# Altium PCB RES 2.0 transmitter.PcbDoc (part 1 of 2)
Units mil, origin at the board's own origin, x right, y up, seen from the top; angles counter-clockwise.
Board outline 3335 x 2413 mil, 2 copper layers (Top Layer, Bottom Layer); 59 components, 51 nets, 223 pads, 116 vias.
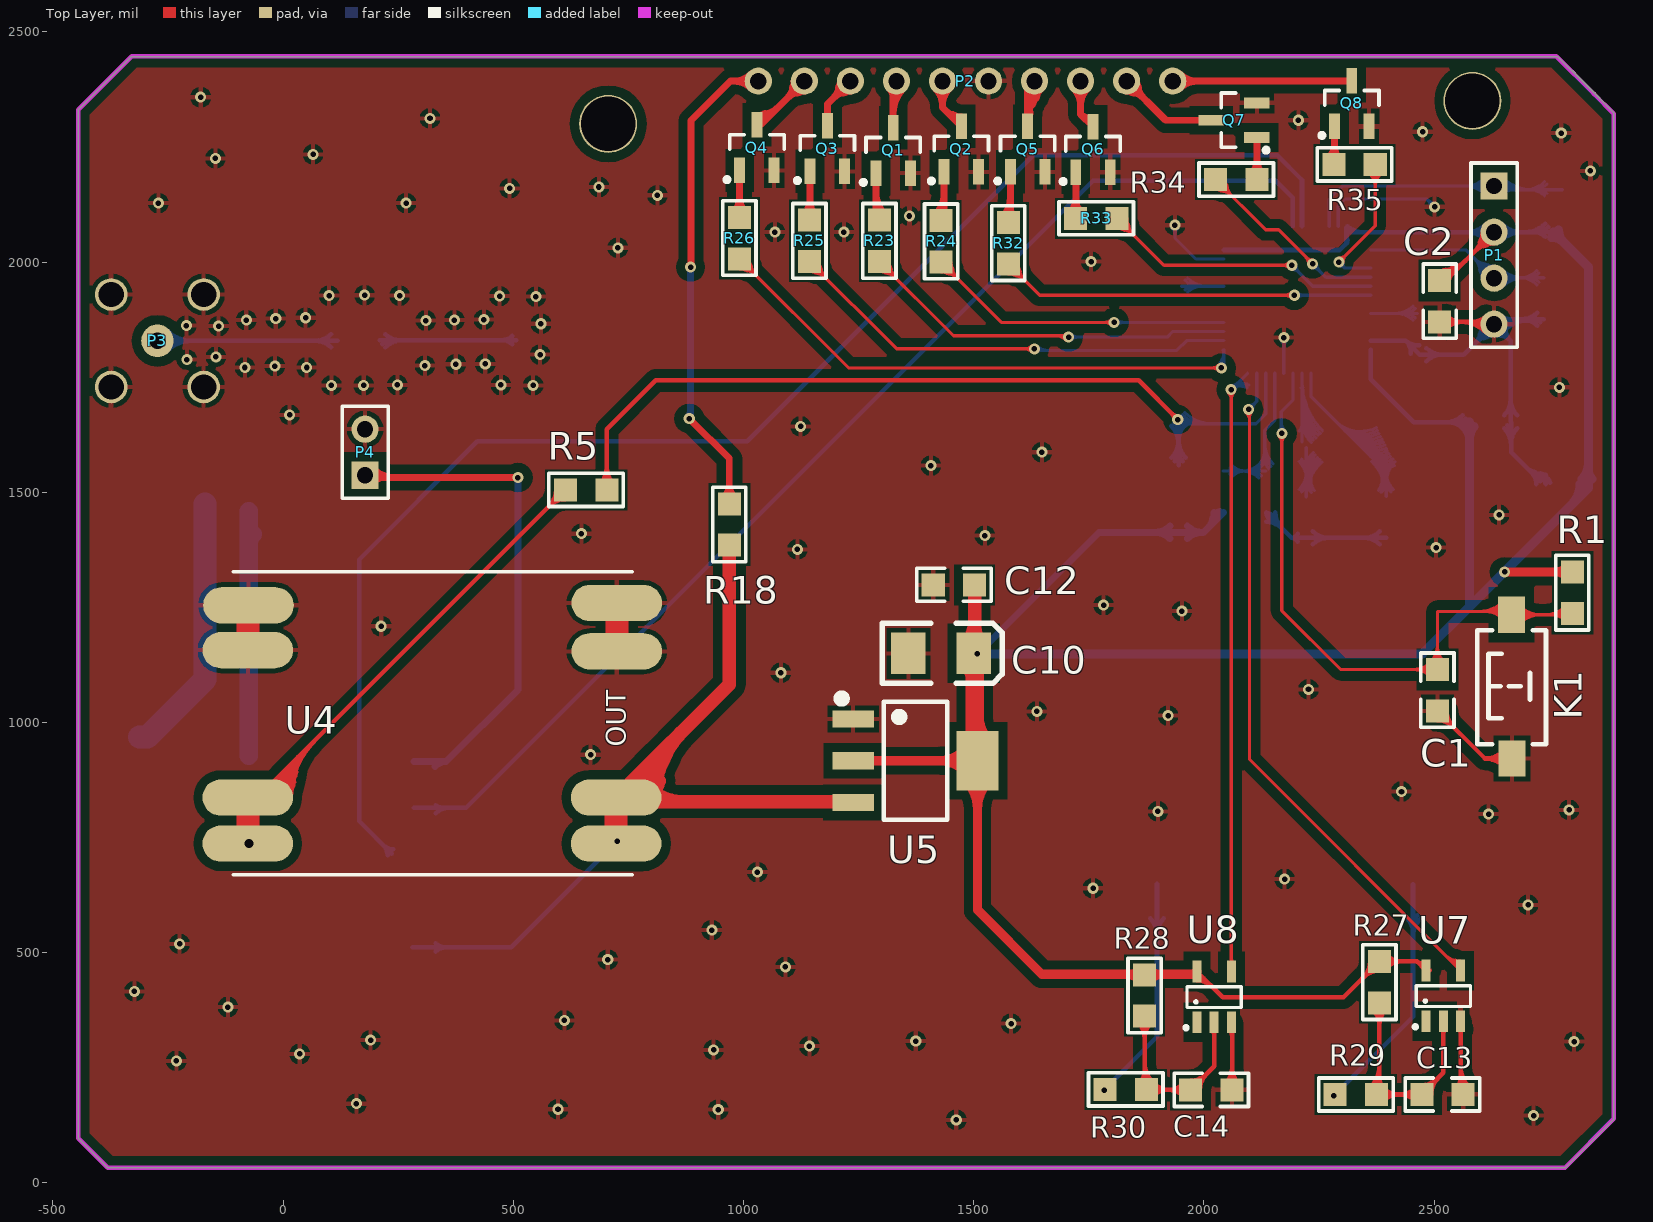
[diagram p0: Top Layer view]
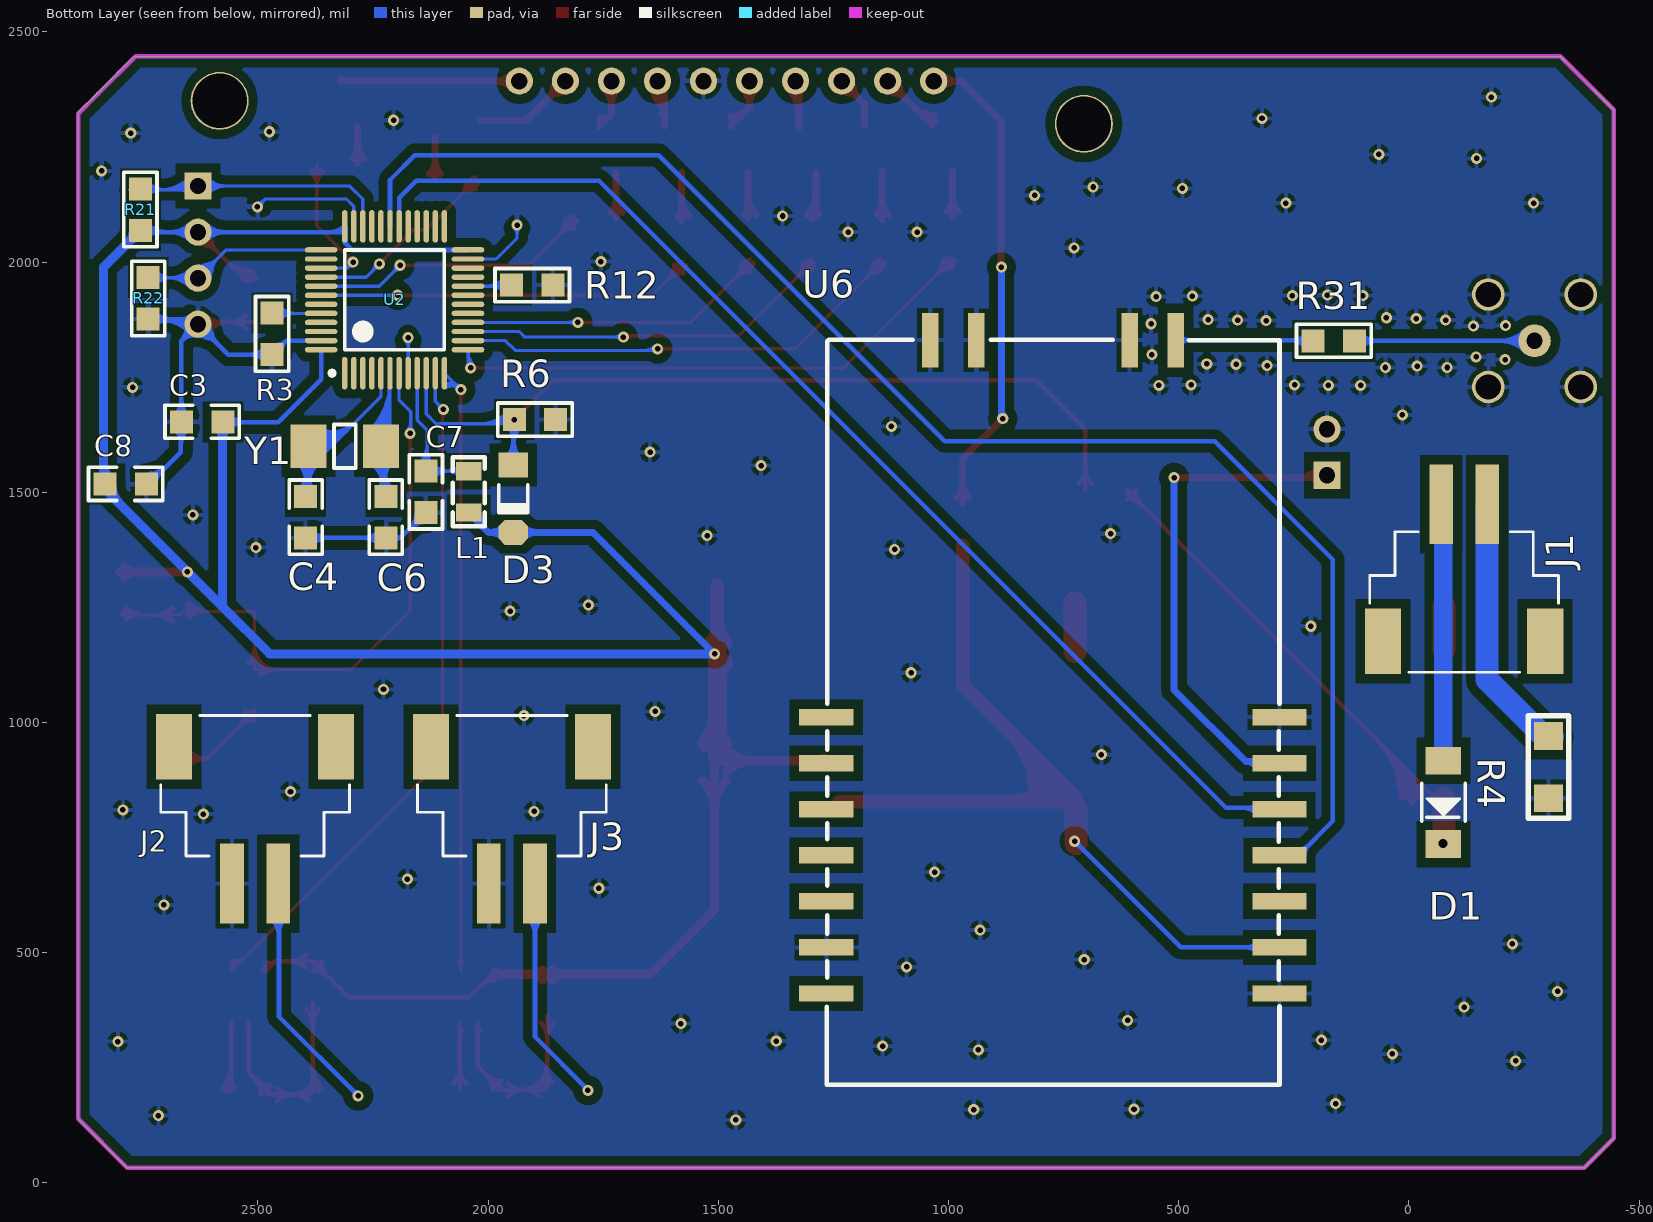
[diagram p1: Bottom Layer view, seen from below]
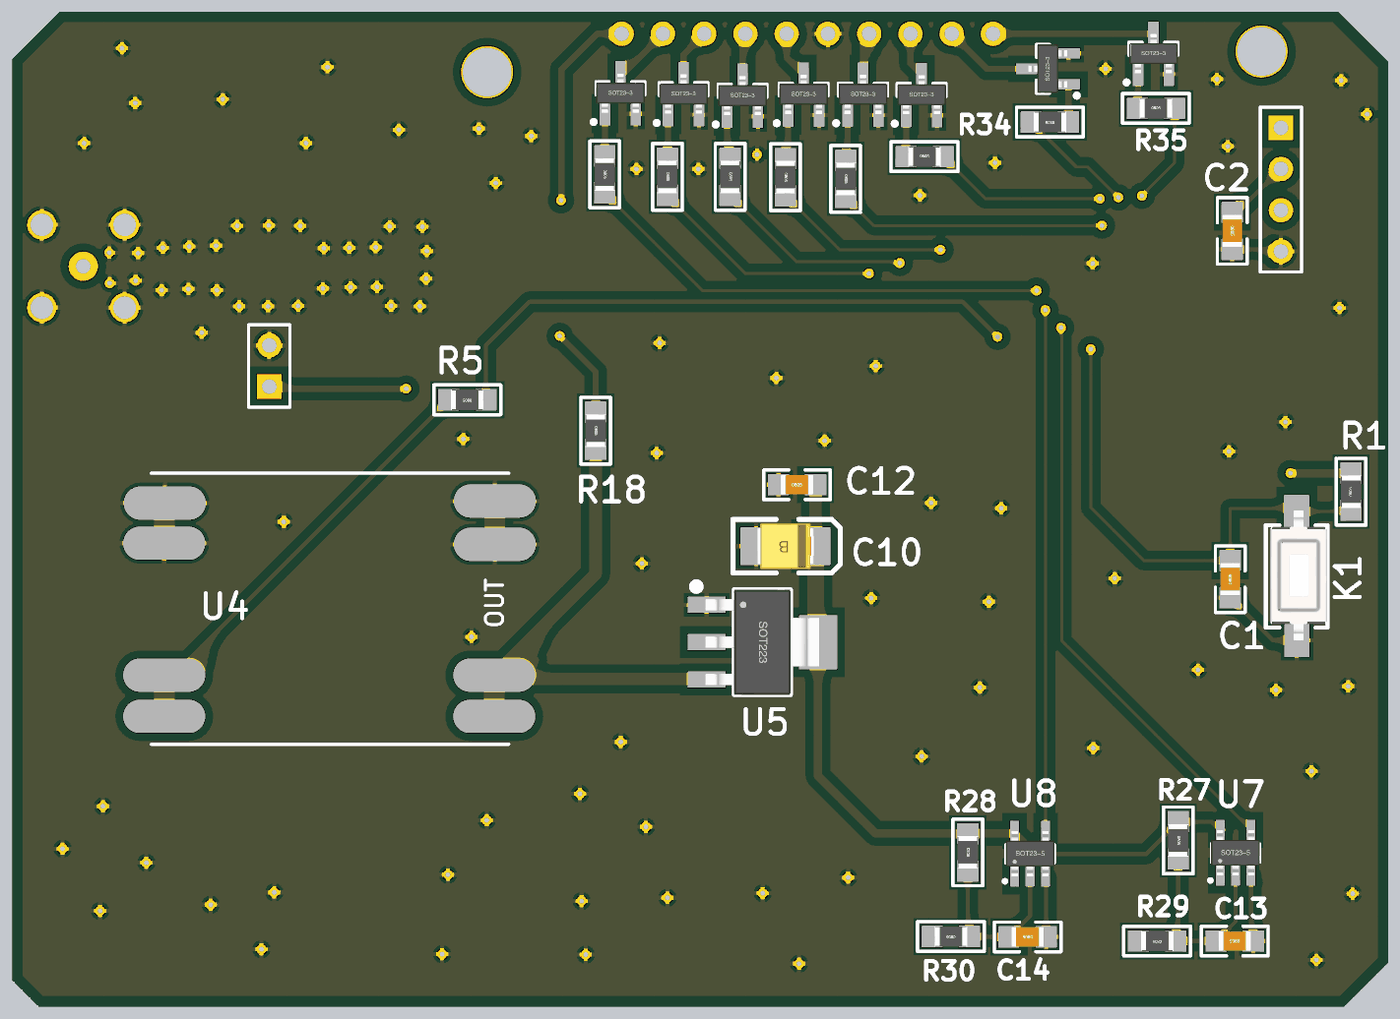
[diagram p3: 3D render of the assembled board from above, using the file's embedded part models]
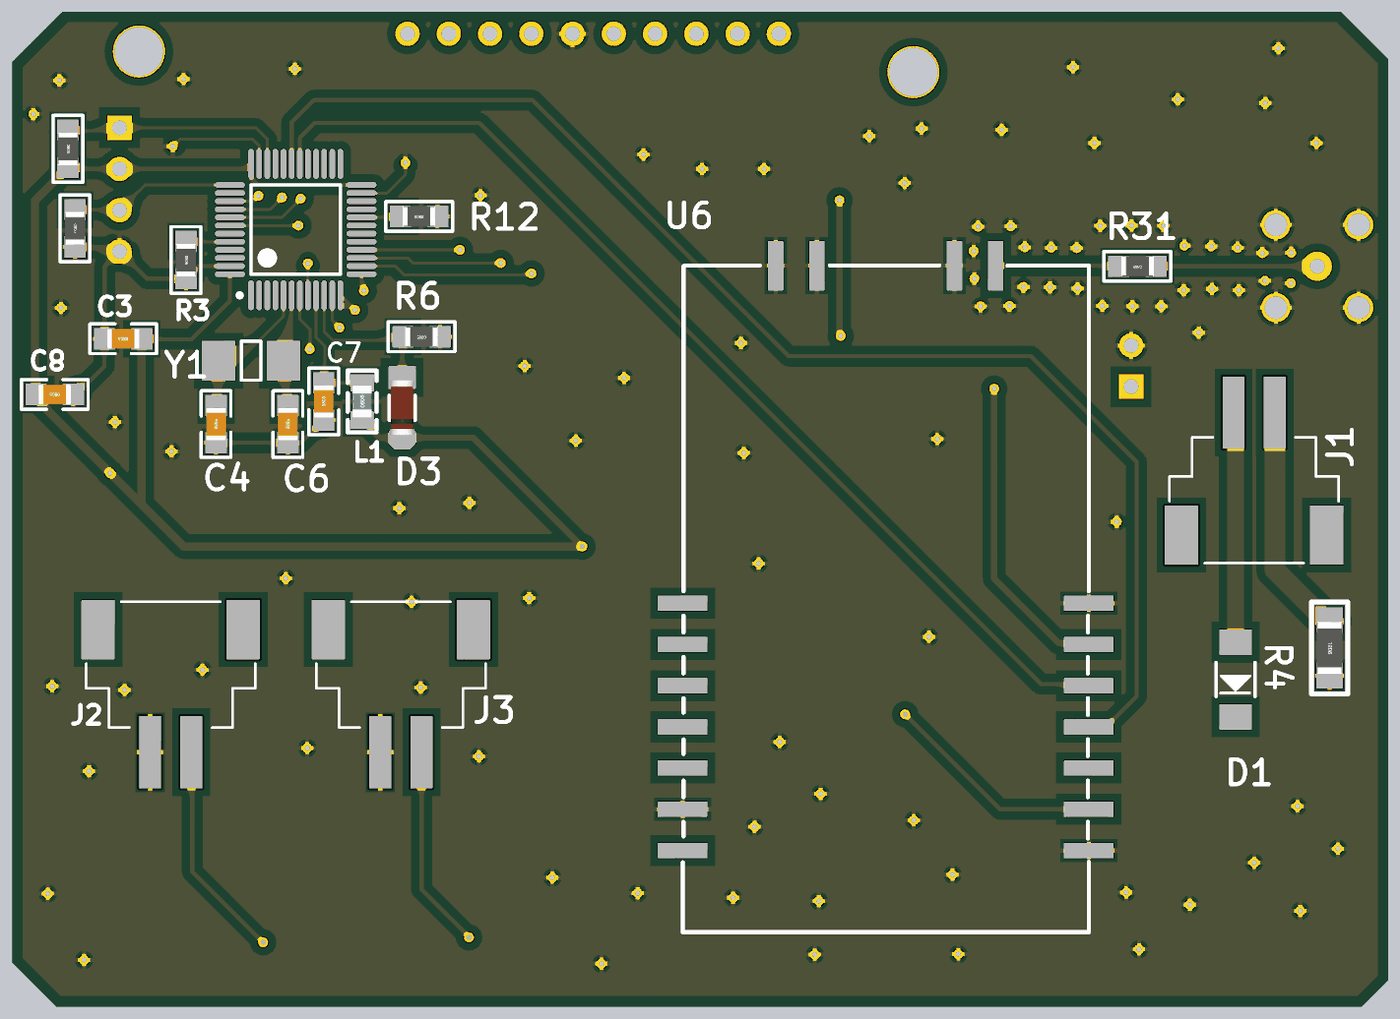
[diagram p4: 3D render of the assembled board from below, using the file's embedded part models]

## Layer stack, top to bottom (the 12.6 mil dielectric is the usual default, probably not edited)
Top Solder: solder mask 0.4, Solder Resist, Dk 3.5
Top Layer: signal copper 1.4
Dielectric1: dielectric 12.6, FR-4, Dk 4.8
Bottom Layer: signal copper 1.4
Bottom Solder: solder mask 0.4, Solder Resist, Dk 3.5

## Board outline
2890,171 2890,139 2784,33 2675,33 -381,33 -421,73 -445,97 -445,147 -445,2331 -350,2426 -330,2446 -244,2446 2769,2446 2829,2386 2890,2325 2890,2285

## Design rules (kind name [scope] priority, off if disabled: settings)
Clearance "polygon clearance" [Inpolygon] p1: gap=20 ignorepadtopadclearanceinfootprint=FALSE except(0: Arc-Hole Track-Hole SMDPad-Hole THPad-Hole Via-Hole Fill-Hole Poly-Hole Region-Hole Text-Hole)
Clearance [All] p2: gap=7 ignorepadtopadclearanceinfootprint=FALSE except(0: Arc-Hole Track-Hole SMDPad-Hole THPad-Hole Via-Hole Fill-Hole Poly-Hole Region-Hole Text-Hole)
ComponentClearance [All] p1: gap=5 collisioncheckmode=3 verticalgap=10 showdistances=FALSE
HoleSize [All] p1: absolutevalues=TRUE maxlimit=137.8 minlimit=1 maxpercent=80.000 minpercent=20.000
MinimumSolderMaskSliver [All] p1: minsoldermaskwidth=1
PasteMaskExpansion [All] p1: expansion=1
PlaneClearance [All] p1: clearance=1
PolygonConnect [All] p1: connectstyle=Relief reliefconductorwidth=10 reliefentries=4 polygonreliefangle="90 Angle" airgapwidth=10
RoutingCorners [All] p1: cornerstyle=45-Degree minsetback=1 maxsetback=10000
RoutingVias [All] p1: holewidth=15 width=15 viastyle="Through Hole" minholewidth=12 minwidth=20 maxholewidth=30 maxwidth=40
SilkToSilkClearance [All] p1: silktosilkclearance=1
SilkToSolderMaskClearance [IsPad] p1: minsilkscreentomaskgap=0.1 clearancetoexposedcopper=TRUE
SolderMaskExpansion [All] p1: expansion=3
Width [All] p1: maxlimit=50 minlimit=7 preferedwidth=10
22 further rules are at their usual default settings.

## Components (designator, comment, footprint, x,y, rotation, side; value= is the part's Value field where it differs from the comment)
C1 "Cap vol" "C 0805" 2507,1070 r90 top
C2 "Cap vol" "C 0805" 2512,1915 r270 top
C3 "Cap vol" "C 0805" 2621,1653 r0 bottom
C4 "Cap vol" "C 0805" 2396,1446 r90 bottom
C6 "Cap vol" "C 0805" 2222,1446 r90 bottom
C7 "Cap vol" "C 0805" 2135,1501 r90 bottom
C8 "Cap vol" "C 0805" 2787,1518 r0 bottom
C10 "Cap vol" "CP 3528B" 1429,1150 r180 top
C12 "Cap vol" "C 0805" 1457,1299 r0 top
C13 "Cap vol" "C 0805" 2518,192 r180 top
C14 "Cap vol" "C 0805" 2016,202 r180 top
D1 "SS14" DO-214 -75,826 r270 bottom
D3 "LL4148" LL34 1945,1486 r270 bottom
J1 "XH2.54_2P" XH2.54_2P_SMT -170,1474 r0 bottom
J2 "XH2.54_2P" XH2.54_2P_SMT 2556,650 r180 bottom
J3 "XH2.54_2P" XH2.54_2P_SMT 1998,650 r180 bottom
K1 "Key" "KEY 3.6*2.5 SMD" 2668,1079 r90 top
L1 "Inductor" "L 0805" 2042,1501 r90 bottom
P1 "Header 4" HDR1X4 2630,2165 r270 top
P2 "Header_10H" Header_10H 1032,2393 r90 top
P3 "天线插座" ANT -273,1829 r0 top
P4 "Header 2" HDR1X2 178,1537 r90 top
Q1 "Model" SOT23-3 1325,2243 r0 top
Q2 "Model" SOT23-3 1473,2246 r0 top
Q3 "Model" SOT23-3 1182,2247 r0 top
Q4 "Model" SOT23-3 1029,2249 r0 top
Q5 "Model" SOT23-3 1617,2246 r0 top
Q6 "Model" SOT23-3 1759,2245 r0 top
Q7 "Model" SOT23-3 2065,2308 r90 top
Q8 "Model" SOT23-3 2321,2345 r0 top
R1 "Res" "R 0805" 2800,1282 r90 top
R3 "Res" "R 0805" 2469,1844 r270 bottom
R4 "Res" "R 1206" -303,903 r270 bottom
R5 "Res" "R 0805" 658,1505 r180 top
R6 "Res" "R 0805" 1898,1658 r0 bottom
R12 "Res" "R 0805" 1904,1950 r0 bottom
R18 "Res" "R 0805" 969,1430 r270 top
R21 "Res" "R 0805" 2755,2114 r270 bottom
R22 "Res" "R 0805" 2738,1921 r270 bottom
R23 "Res" "R 0805" 1295,2046 r270 top
R24 "Res" "R 0805" 1429,2045 r270 top
R25 "Res" "R 0805" 1143,2046 r270 top
R26 "Res" "R 0805" 991,2052 r270 top
R27 "Res" "R 0805" 2381,436 r270 top
R28 "Res" "R 0805" 1871,407 r270 top
R29 "Res" "R 0805" 2330,192 r180 top
R30 "Res" "R 0805" 1830,203 r180 top
R31 "Res2" "R 0805" 163,1829 r0 bottom
R32 "Res" "R 0805" 1575,2041 r270 top
R33 "Res" "R 0805" 1766,2095 r0 top
R34 "Res" "R 0805" 2070,2179 r180 top
R35 "Res" "R 0805" 2327,2212 r0 top
U2 "STM32F103C8T6" LQFP48 2203,1918 r180 bottom
U4 "DM02" DM02 324,997 r180 top
U5 "AMS1117" SOT223 1373,917 r270 top
U6 "USART_Module" USART_Module 778,1121 r0 bottom
U7 "SN74LVC1G14" SOT23-5 2520,406 r0 top
U8 "SN74LVC1G14" SOT23-5 2022,404 r0 top
Y1 "Freq" XTAL-5032 2311,1600 r0 bottom

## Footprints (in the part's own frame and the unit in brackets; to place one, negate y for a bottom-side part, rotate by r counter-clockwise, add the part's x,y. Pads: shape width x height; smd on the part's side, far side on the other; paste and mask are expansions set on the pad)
ANT [mm]
  round 1.8 hole 0.9: 1(0,0)
  round 1.8 hole 1.4: 2(-2.55,2.55) 3(2.55,2.55) 4(-2.55,-2.55) 5(2.55,-2.55)
"C 0805" [mil]
  rect 50x50 smd: 1(-45,0) 2(45,0)
  silkscreen extent -81,-36 81,36, body extent -39,-24 39,24, height 20
"CP 3528B" [mil]
  rect 75x90 smd: 1(-70.86,0) 2(70.87,0)
  silkscreen extent -132,-65 128,65, body extent -69,-55 69,55, height 75
DM02 [mm]
  oval 5x2 smd: 1(-10.143,6.604) 2(-10.143,4.064) 3(-10.177,-4.001) 4(-10.177,-6.668) 5(10.143,-6.54) 6(10.177,-4.064) 7(10.177,4.064) 8(10.177,6.604)
  silkscreen extent -11.03,-8.38 10.97,8.32
DO-214 [mil]
  rect 60x76.77 smd: 1(-91.03,0) 2(90.07,0)
  silkscreen extent -42,-47 41,47, body extent -84,-47 83,47, height 118
HDR1X2 [mm] "Connector; Header; 2 Position"
  rect 1.5x1.5 hole 0.9: 1(0,0)
  round 1.5 hole 0.9: 2(2.54,0)
  silkscreen extent -1.27,-1.27 3.81,1.27
HDR1X4 [mm] "Connector; Header; 4 Position"
  rect 1.5x1.5 hole 0.9: 1(0,0)
  round 1.5 hole 0.9: 2(2.54,0) 3(5.08,0) 4(7.62,0)
  silkscreen extent -1.27,-1.27 8.89,1.27
Header_10H [mm]
  round 1.5 hole 0.9: 1(0,0) 2(0,-2.54) 3(0,-5.08) 4(0,-7.62) 5(0,-10.16) 6(0,-12.7) 7(0,-15.24) 8(0,-17.78) 9(0,-20.32) 10(0,-22.86)
"KEY 3.6*2.5 SMD" [mm]
  rect 2x1.5 smd: 1(-3.996,-0.02) 2(3.937,0)
  silkscreen extent -3.21,-1.9 3.09,1.9, body extent -4,-1.88 4,1.62, height 2.59
"L 0805" [mil]
  rect 40x55 smd: 1(-45,0) 2(45,0)
  silkscreen extent -75,-35 75,35, body extent -39,-24 39,24, height 35
LL34 [mm]
  rect 1.37x1.62 smd: 1(-1.855,0)
  oct 1.37x1.62 smd: 2(1.855,0)
  silkscreen extent -0.76,-0.8 0.78,0.8, body extent -1.7,-0.75 1.7,0.75, height 1.5
LQFP48 [mm]
  oval 0.3x1.8 smd: 1(-2.75,-4.05) 2(-2.25,-4.05) 3(-1.75,-4.05) 4(-1.25,-4.05) 5(-0.75,-4.05) 6(-0.25,-4.05) 7(0.25,-4.05) 8(0.75,-4.05) 9(1.25,-4.05) 10(1.75,-4.05) 11(2.25,-4.05) 12(2.75,-4.05) 25(2.75,4.05) 26(2.25,4.05) 27(1.75,4.05) 28(1.25,4.05) 29(0.75,4.05) 30(0.25,4.05) 31(-0.25,4.05) 32(-0.75,4.05) 33(-1.25,4.05) 34(-1.75,4.05) 35(-2.25,4.05) 36(-2.75,4.05)
  oval 1.8x0.3 smd: 13(4.05,-2.75) 14(4.05,-2.25) 15(4.05,-1.75) 16(4.05,-1.25) 17(4.05,-0.75) 18(4.05,-0.25) 19(4.05,0.25) 20(4.05,0.75) 21(4.05,1.25) 22(4.05,1.75) 23(4.05,2.25) 24(4.05,2.75) 37(-4.05,2.75) 38(-4.05,2.25) 39(-4.05,1.75) 40(-4.05,1.25) 41(-4.05,0.75) 42(-4.05,0.25) 43(-4.05,-0.25) 44(-4.05,-0.75) 45(-4.05,-1.25) 46(-4.05,-1.75) 47(-4.05,-2.25) 48(-4.05,-2.75)
  silkscreen extent -3.58,-4.17 2.75,2.75, body extent -3.5,-3.5 3.5,3.5, height 1.6
"R 0805" [mil]
  rect 50x50 smd: 1(-45,0) 2(45,0)
  silkscreen extent -81,-36 81,36, body extent -39,-25 39,25, height 20
"R 1206" [mil]
  rect 60x62.99 smd: 1(-67.5,0) 2(67.5,0)
  silkscreen extent -111,-44 112,44, body extent -63,-31 63,31, height 22
SOT23-3 [mm]
  rect 0.6x1.4 smd: 1(-0.95,-1.27) 2(0.95,-1.27) 3(0,1.244)
  silkscreen extent -1.78,-1.9 1.5,0.7, body extent -1.5,-1.2 1.5,1.2, height 1.05
SOT23-5 [mm]
  rect 0.5x1.2 smd: 1(-0.95,-1.4) 2(0,-1.4) 3(0.95,-1.4) 4(0.95,1.4) 5(-0.95,1.4)
  silkscreen extent -1.63,-1.78 1.5,0.56, body extent -1.5,-1.4 1.5,1.4, height 1.15
SOT223 [mm]
  rect 0.95x2.3 smd: 1(-2.3,-3.429) 2(0,-3.429) 3(2.3,-3.429)
  rect 3.3x2.3 smd: 2(0,3.429)
  silkscreen extent -3.63,-4.26 3.25,1.75, body extent -3.25,-3.51 3.25,3.51, height 1.65
USART_Module [mm]
  rect 3x0.9 smd: 1(-12.627,2.78) 2(-12.627,5.32) 3(-12.627,7.86) 4(-12.627,10.4) 5(-12.627,12.94) 6(-12.627,15.48) 7(-12.627,18.02) 8(12.373,18.02) 9(12.373,15.48) 10(12.373,12.94) 11(12.373,10.4) 12(12.373,7.86) 13(12.373,2.78) 14(12.373,5.32)
  rect 0.9x3 smd: 15(6.643,-18.02) 16(4.103,-18.02) 17(-4.357,-18.02) 18(-6.897,-18.02)
  silkscreen extent -12.63,-18.03 12.36,23.05
XH2.54_2P_SMT [mm]
  rect 1.3x4.4 smd mask+0.152: 1(0,0) 2(2.54,0)
  rect 2x3.6 smd mask+0.152: 3(5.74,7.554)
  rect 2x3.6 smd: 4(-3.2,7.554)
  silkscreen extent -3.94,1.52 6.48,9.27
XTAL-5032 [mm]
  rect 2x2.4 smd: 1(-2,0) 2(2,0)
  silkscreen extent -0.6,-1.2 0.6,1.2, body extent -2.6,-1.7 2.6,1.7, height 3.4

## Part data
C1 C2 C3 C4 C6 C7 C8 C12 C13 C14: library part Cap, "无极性电容"
C10: library part Cap_Pol, "极性电容"
D1: library part Diode, "肖特基（快恢复）二极管"
D3: library part Diode, "开关二极管"
J1: "XH2.54Header,2-pin"
K1: "按键"
L1: "电感"
P1: "Header, 4-Pin"
P4: "Header, 2-Pin"
Q1 Q2 Q3 Q4 Q5 Q6 Q7 Q8: library part Transistor_NPN, "NPN三极管"
R1 R3 R4 R5 R6 R12 R18 R21 R22 R23 R24 R25 R26 R27 R28 R29 R30 R32 R33 R34 R35: library part Resistor, "电阻"
R31: "Resistor"
U2: "Micro controller"
U4: "开关型DC-DC变换器"
U5: "线性稳压器"
U6: library part RES
U7 U8: "单路施密特反相器"
Y1: library part XTAL, "晶振"

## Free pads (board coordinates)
  round 125.98 hole 118.11: 1(706,2300) 2(2583,2350)

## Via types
v1: diameter 24, hole 12, Top Layer to Bottom Layer, 115 vias
v2: diameter 40, hole 20, Top Layer to Bottom Layer, 1 vias

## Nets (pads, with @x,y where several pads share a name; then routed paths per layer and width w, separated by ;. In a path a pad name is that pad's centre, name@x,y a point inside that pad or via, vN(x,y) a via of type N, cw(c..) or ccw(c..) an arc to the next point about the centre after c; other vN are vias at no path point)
ADC: D3.1 R5.1 R6.2 U2.10 | length 3224.3
  Top Layer w10: R5.1@703,1505 703,1637 809,1743 1858,1743 v1(1943,1658) ; 703,1553.28 cw(c654.72,1553.28) 688.86,1519.14 ccw(c654.72,1553.28) 703,1553.28 ; 703,1553.28 ccw(c751.28,1553.28) 717.14,1519.14 cw(c751.28,1553.28) 703,1553.28 ; 1931.05,1669.95 cw(c1919.1,1658) 1936,1658 ccw(c1919.1,1658) 1931.05,1669.95 ; 1931.05,1669.95 ccw(c1943,1681.9) 1943,1665 cw(c1943,1681.9) 1931.05,1669.95
  Bottom Layer w7: v1(1943,1658) 1952,1649 2113,1649 2134.1,1670.1 U2.10@2134.1,1758.55 ; R6.2@1947.21,1650.62 cw(c1952.95,1640.57) R6.2@1958.73,1650.59 ; R6.2@1948.43,1651.46 cw(c1959.34,1638.33) R6.2@1967.88,1653.12 ; R6.2@1951.21,1660.2 ccw(c1966.25,1664.23) R6.2@1958.47,1650.74 ; R6.2@1959.18,1658.14 ccw(c1952.5,1646.57) R6.2@1943.96,1656.85 ; R6.2@1943.94,1656.83 cw(c1951.59,1647.28) R6.2@1957.7,1657.88 ; R6.2@1943.94,1656.83 cw(c1951.59,1647.28) R6.2@1957.7,1657.88 ; R6.2@1943.94,1656.83 cw(c1951.59,1647.28) R6.2@1957.7,1657.88 ; R6.2@1948.31,1651.37 cw(c1958.46,1638.7) R6.2@1966.57,1652.76 ; R6.2@1948.31,1651.37 cw(c1958.46,1638.7) R6.2@1966.57,1652.76 ; R6.2@1948.31,1651.37 cw(c1958.46,1638.7) R6.2@1966.57,1652.76 ; R6.2@1939.11,1654.11 ccw(c1951.45,1666.45) 1951.45,1649 cw(c1951.45,1666.45) R6.2@1939.11,1654.11 ; R6.2@1944.06,1659.06 ccw(c1968.35,1683.35) 1968.35,1649 cw(c1968.35,1683.35) R6.2@1944.06,1659.06 ; R6.2@1948.3,1663.3 ccw(c1982.83,1697.83) 1982.83,1649 cw(c1982.83,1697.83) R6.2@1948.3,1663.3 ; R6.2@1949.01,1664.01 ccw(c1985.25,1700.25) 1985.25,1649 cw(c1985.25,1700.25) R6.2@1949.01,1664.01 ; R6.2@1953.25,1668.25 ccw(c1999.73,1714.73) 1999.73,1649 cw(c1999.73,1714.73) R6.2@1953.25,1668.25 ; R6.2@1958.2,1642.8 cw(c1973.18,1627.82) 1973.18,1649 ccw(c1973.18,1627.82) R6.2@1958.2,1642.8 ; R6.2@1958.2,1673.2 ccw(c2016.63,1731.63) 2016.63,1649 cw(c2016.63,1731.63) R6.2@1958.2,1673.2
  Bottom Layer w10: D3.1@1945,1559.03 R6.2@1945,1656 ; 1945,1587.93 cw(c1916.11,1587.93) 1936.54,1567.49 ccw(c1916.11,1587.93) 1945,1587.93 ; 1945,1587.93 ccw(c1973.89,1587.93) 1953.46,1567.49 cw(c1973.89,1587.93) 1945,1587.93 ; 1945,1612.07 cw(c1891.96,1612.07) 1929.47,1574.57 ccw(c1891.96,1612.07) 1945,1612.07 ; 1945,1612.07 ccw(c1998.04,1612.07) 1960.53,1574.57 cw(c1998.04,1612.07) 1945,1612.07 ; R6.2@1928.86,1643.86 cw(c1889.89,1604.89) 1945,1604.89 ccw(c1889.89,1604.89) R6.2@1928.86,1643.86 ; R6.2@1935.93,1650.93 cw(c1914.03,1629.03) 1945,1629.03 ccw(c1914.03,1629.03) R6.2@1935.93,1650.93 ; R6.2@1938.05,1653.05 cw(c1921.27,1636.27) 1945,1636.27 ccw(c1921.27,1636.27) R6.2@1938.05,1653.05 ; 1945,1614.54 cw(c1986.46,1614.54) 1957.14,1643.86 ccw(c1986.46,1614.54) 1945,1614.54 ; R6.2@1945,1645.93 cw(c1955.07,1645.93) 1947.95,1653.05 ccw(c1955.07,1645.93) R6.2@1945,1645.93
ANT: P3.1 R31.1 | length 928.5
  Bottom Layer w10: P3.1@-273,1829 R31.1@118,1829 ; -223.67,1829 cw(c-223.67,1878.33) -258.55,1843.45 ccw(c-223.67,1878.33) -223.67,1829 ; -223.67,1829 ccw(c-223.67,1779.67) -258.55,1814.55 cw(c-223.67,1779.67) -223.67,1829 ; -199.53,1829 cw(c-199.53,1902.47) -251.48,1850.52 ccw(c-199.53,1902.47) -199.53,1829 ; -199.53,1829 ccw(c-199.53,1755.53) -251.48,1807.48 cw(c-199.53,1755.53) -199.53,1829 ; 69.72,1829 cw(c69.72,1780.72) 103.86,1814.86 ccw(c69.72,1780.72) 69.72,1829 ; 69.72,1829 ccw(c69.72,1877.28) 103.86,1843.14 cw(c69.72,1877.28) 69.72,1829
BLUE: P2.3 Q3.3 | length 355.8
  Top Layer w15: Q3.3@1182,2295.97 1182,2343 P2.3@1232,2393 ; 1205.88,2377.71 cw(c1236.83,2369.42) P2.3@1230.4,2400.81 ; 1216.71,2366.88 ccw(c1208.42,2397.83) P2.3@1239.81,2391.4 ; 1194.4,2355.4 cw(c1232,2317.79) 1232,2370.97 ccw(c1232,2317.79) 1194.4,2355.4 ; 1194.4,2355.4 ccw(c1156.79,2393) 1209.97,2393 cw(c1156.79,2393) 1194.4,2355.4
GND_D: C1.1 C2.2 C3.2 C4.1 C6.1 C7.1 C8.1 C10.2 C12.1 C13.1 C14.1 J2.1 J3.1 K1.1 P1.4 P2.6 P3.2 P3.3 P3.4 P3.5 P4.2 Q1.2 Q2.2 Q3.2 Q4.2 Q5.2 Q6.2 Q7.2 Q8.2 R3.2 R4.2 R6.1 R12.1 R22.2 U2.8 U2.23 U2.35 U2.47 U4.3 U4.4 U4.5 U4.6 U5.1 U6.1 U6.7 U6.9 U6.15 U6.16 U6.17 U7.3 U8.3 | length 6865.7
  Top Layer w10: C14.1@2061,202 U8.3@2061,347.29 ; C2.2@2512,1870 P1.4@2625,1870 ; 2532.2,998.25 cw(c2541.24,1032.01) C1.1@2507,1025 ; 2533.75,999.8 ccw(c2499.99,990.76) C1.1@2507,1025 ; C13.1@2557.4,197.6 U7.3@2557.4,350.89 ; K1.1@2668.79,921.69 2610.31,921.69 ; 2061,250.28 cw(c2012.72,250.28) 2046.86,216.14 ccw(c2012.72,250.28) 2061,250.28 ; 2061,250.28 ccw(c2109.28,250.28) 2075.14,216.14 cw(c2109.28,250.28) 2061,250.28 ; C1.1@2507,1025 2610.31,921.69 ; 2541.14,990.86 cw(c2575.28,1025) 2527,1025 ccw(c2575.28,1025) 2541.14,990.86 ; 2541.14,990.86 ccw(c2507,956.72) 2507,1005 cw(c2507,956.72) 2541.14,990.86 ; 2557.4,325.41 cw(c2569.1,325.41) 2560.83,333.68 ccw(c2569.1,325.41) 2557.4,325.41 ; 2557.4,325.41 ccw(c2545.71,325.41) 2553.98,333.68 cw(c2545.71,325.41) 2557.4,325.41 ; 2560.28,1870 cw(c2560.28,1918.28) 2526.14,1884.14 ccw(c2560.28,1918.28) 2560.28,1870 ; 2560.28,1870 ccw(c2560.28,1821.72) 2526.14,1855.86 cw(c2560.28,1821.72) 2560.28,1870 ; 2582.86,1870 cw(c2582.86,1817.86) 2619.73,1854.73 ccw(c2582.86,1817.86) 2582.86,1870 ; 2582.86,1870 ccw(c2582.86,1912.14) 2612.66,1882.34 cw(c2582.86,1912.14) 2582.86,1870 ; 2610.32,921.69 cw(c2610.32,864.26) 2651.29,904.5 ccw(c2610.32,864.26) 2610.32,921.69 ; 2610.32,921.69 ccw(c2610.32,979.11) 2651.29,938.87 cw(c2610.32,979.11) 2610.32,921.69 ; 2634.16,921.69 cw(c2634.16,887.67) 2658.42,911.51 ccw(c2634.16,887.67) 2634.16,921.69 ; 2634.16,921.69 ccw(c2634.16,955.7) 2658.42,931.87 cw(c2634.16,955.7) 2634.16,921.69 ; U8.3@2055.98,331.68 cw(c2043.86,319.56) 2061,319.56 ccw(c2043.86,319.56) U8.3@2055.98,331.68 ; C13.1@2548.86,206.14 ccw(c2528.22,226.78) 2557.4,226.78 cw(c2528.22,226.78) C13.1@2548.86,206.14 ; 2557.4,229.65 ccw(c2600.65,229.65) 2570.07,199.07 cw(c2600.65,229.65) 2557.4,229.65 ; 2557.4,253.79 ccw(c2624.79,253.79) 2577.14,206.14 cw(c2624.79,253.79) 2557.4,253.79 ; 2558.71,1870 cw(c2558.71,1793.71) 2612.66,1847.66 ccw(c2558.71,1793.71) 2558.71,1870
  Top Layer w50: U4.6@-76.69,1157 U4.5@-76.69,1253.13 ; U4.3@724.69,1154.5 U4.4@724.69,1259.5
  Bottom Layer w7: v1(1937,2080) 1937,2052 1982.42,2006.58 U2.23@2043.55,2006.58 ; U2.8@2173.47,1758.55 v1@2173.47,1840.53 ; U2.35@2291.58,2077.45 2291.58,2121.29 2307.29,2137 2484,2137 v1(2501,2120) ; 1937,2059.48 cw(c1957.52,2059.48) 1943.01,2073.99 ccw(c1957.52,2059.48) 1937,2059.48 ; 1937,2059.48 ccw(c1916.48,2059.48) 1930.99,2073.99 cw(c1916.48,2059.48) 1937,2059.48 ; 2173.47,1815.48 cw(c2193.99,1815.48) 2179.48,1829.99 ccw(c2193.99,1815.48) 2173.47,1815.48 ; 2173.47,1815.48 ccw(c2152.95,1815.48) 2167.46,1829.99 cw(c2152.95,1815.48) 2173.47,1815.48 ; 2486.49,2134.51 cw(c2471.98,2120) 2492.5,2120 ccw(c2471.98,2120) 2486.49,2134.51 ; 2486.49,2134.51 ccw(c2501,2149.02) 2501,2128.5 cw(c2501,2149.02) 2486.49,2134.51
  Bottom Layer w10: 2160.2,1429.25 cw(c2169.24,1463.01) C7.1@2135,1456 ; 2161.75,1430.8 ccw(c2127.99,1421.76) C7.1@2135,1456 ; U2.47@2362.45,1829.42 2438.58,1829.42 ; C4.1@2396,1401 C6.1@2222,1401 2190,1401 ; 2599.48,1842.65 cw(c2636.61,1832.7) P1.4@2628.9,1870.36 ; 2607.65,1834.48 ccw(c2597.7,1871.61) P1.4@2635.36,1863.9 ; C3.2@2666,1653 2666,1829 ; C3.2@2667,1652 2667,1587 C8.1@2730,1524 ; 2713.24,1545.71 cw(c2702.56,1505.84) C8.1@2742,1518 ; C8.1@2730.72,1541.02 cw(c2722.98,1512.14) C8.1@2751.56,1520.95 ; R22.2@2738,1876 2641,1876 P1.4@2630,1865 ; C7.1@2135,1456 2190,1401 ; 2169.14,1421.86 cw(c2203.28,1456) 2155,1456 ccw(c2203.28,1456) 2169.14,1421.86 ; 2169.14,1421.86 ccw(c2135,1387.72) 2135,1436 cw(c2135,1387.72) 2169.14,1421.86 ; 2190,1401 cw(c2190,1385.4) 2204.02,1392.24 ccw(c2190,1385.4) 2190,1401 ; 2190,1401 ccw(c2190,1416.6) 2204.02,1409.76 cw(c2190,1416.6) 2190,1401 ; 2270.28,1401 cw(c2270.28,1449.28) 2236.14,1415.14 ccw(c2270.28,1449.28) 2270.28,1401 ; 2270.28,1401 ccw(c2270.28,1352.72) 2236.14,1386.86 cw(c2270.28,1352.72) 2270.28,1401 ; 2347.72,1401 cw(c2347.72,1352.72) 2381.86,1386.86 ccw(c2347.72,1352.72) 2347.72,1401 ; 2347.72,1401 ccw(c2347.72,1449.28) 2381.86,1415.14 cw(c2347.72,1449.28) 2347.72,1401 ; 2438.58,1829.42 cw(c2412.95,1803.78) 2449.07,1800.7 ccw(c2412.95,1803.78) 2438.58,1829.42 ; 2438.58,1829.42 ccw(c2464.22,1855.05) 2467.3,1818.93 cw(c2464.22,1855.05) 2438.58,1829.42 ; 2438.58,1829.42 R3.2@2469,1799 2564,1799 P1.4@2630,1865 ; 2517.28,1799 cw(c2517.28,1847.28) 2483.14,1813.14 ccw(c2517.28,1847.28) 2517.28,1799 ; 2517.28,1799 ccw(c2517.28,1750.72) 2483.14,1784.86 cw(c2517.28,1750.72) 2517.28,1799 ; 2588.13,1823.13 cw(c2630,1781.26) 2630,1840.47 ccw(c2630,1781.26) 2588.13,1823.13 ; 2588.13,1823.13 ccw(c2546.26,1865) 2605.47,1865 cw(c2546.26,1865) 2588.13,1823.13 ; 2605.2,1840.2 cw(c2630,1815.4) 2630,1850.47 ccw(c2630,1815.4) 2605.2,1840.2 ; 2605.2,1840.2 ccw(c2580.4,1865) 2615.47,1865 cw(c2580.4,1865) 2605.2,1840.2 ; P1.4@2630,1865 2666,1829 ; 2651.32,1843.68 cw(c2668.31,1860.67) 2644.44,1863.37 ccw(c2668.31,1860.67) 2651.32,1843.68 ; 2651.32,1843.68 ccw(c2634.33,1826.69) 2631.63,1850.56 cw(c2634.33,1826.69) 2651.32,1843.68 ; 2666,1701.28 cw(c2617.72,1701.28) 2651.86,1667.14 ccw(c2617.72,1701.28) 2666,1701.28 ; 2666,1701.28 ccw(c2714.28,1701.28) 2680.14,1667.14 cw(c2714.28,1701.28) 2666,1701.28 ; 2666,1829 cw(c2694.69,1857.69) 2654.37,1862.25 ccw(c2694.69,1857.69) 2666,1829 ; 2666,1829 ccw(c2637.31,1800.31) 2632.75,1840.63 cw(c2637.31,1800.31) 2666,1829 ; 2689.72,1876 cw(c2689.72,1827.72) 2723.86,1861.86 ccw(c2689.72,1827.72) 2689.72,1876 ; 2689.72,1876 ccw(c2689.72,1924.28) 2723.86,1890.14 cw(c2689.72,1924.28) 2689.72,1876 ; 2693.95,1872.25 cw(c2699.49,1840.02) R22.2@2723.39,1862.35 ; 2693.95,1872.25 cw(c2699.49,1840.02) R22.2@2723.39,1862.35 ; 2693.95,1872.25 cw(c2699.49,1840.02) R22.2@2723.39,1862.35 ; 2698.73,1873.07 ccw(c2692.73,1907.99) R22.2@2721.67,1887.54 ; 2698.73,1873.07 ccw(c2692.73,1907.99) R22.2@2721.67,1887.54 ; 2698.73,1873.07 ccw(c2692.73,1907.99) R22.2@2721.67,1887.54 ; 2712.22,1875.39 cw(c2715.69,1855.16) R22.2@2730.69,1869.17 ; 2712.22,1875.39 cw(c2715.69,1855.16) R22.2@2730.69,1869.17 ; 2712.22,1875.39 cw(c2715.69,1855.16) R22.2@2730.69,1869.17 ; P1.4@2633.2,1861.8 cw(c2667.49,1827.51) 2667.49,1876 ccw(c2667.49,1827.51) P1.4@2633.2,1861.8 ; P1.4@2640.27,1854.73 cw(c2691.63,1803.37) 2691.63,1876 ccw(c2691.63,1803.37) P1.4@2640.27,1854.73 ; P1.4@2647.34,1847.66 cw(c2715.77,1779.23) 2715.77,1876 ccw(c2715.77,1779.23) P1.4@2647.34,1847.66 ; P1.4@2647.34,1882.34 ccw(c2662.66,1897.66) 2662.66,1876 cw(c2662.66,1897.66) P1.4@2647.34,1882.34 ; C3.2@2651.86,1638.86 cw(c2615.3,1602.3) 2667,1602.3 ccw(c2615.3,1602.3) C3.2@2651.86,1638.86 ; C3.2@2658.93,1645.93 cw(c2639.44,1626.44) 2667,1626.44 ccw(c2639.44,1626.44) C3.2@2658.93,1645.93 ; 2667,1607.13 cw(c2711.87,1607.13) 2680.14,1638.86 ccw(c2711.87,1607.13) 2667,1607.13 ; 2697.62,1556.38 ccw(c2742,1600.77) 2742,1538 cw(c2742,1600.77) 2697.62,1556.38 ; 2712.1,1541.9 cw(c2688.2,1518) 2722,1518 ccw(c2688.2,1518) 2712.1,1541.9 ; 2714.69,1539.31 ccw(c2742,1566.63) 2742,1528 cw(c2742,1566.63) 2714.69,1539.31
  other v1: 1462,137 2716,146 945,159 597,160 159,172 -232,265 36,280 935,289 1143,297 2804,307 1374,308 190,310 1581,346 611,353 -120,382 -323,416 1091,469 705,485 -225,519 931,549 2704,604 1759,640 2175,660 1030,675 2618,801 1900,807 2793,810 2429,850 668,930 1922,1015 1637,1024 2227,1072 1081,1108 213,1209 1952,1242 1782,1255 1117,1376 2504,1380 1524,1406 648,1410 2641,1451 1407,1558 1648,1587 1124,1643 14,1668 2772,1728 105,1732 175,1732 543,1732 248,1733 473,1733 -83,1771 51,1771 -18,1774 308,1775 375,1778 439,1779 -209,1788 -146,1794 558,1799 2173.47,1836 -140,1861 -210,1862 560,1866 310,1873 -80,1874 372,1874 436,1875 -16,1877 49,1879 549,1925 470,1926 100,1927 253,1927 177,1928 1755,2001 727,2031 1068,2065 1218,2065 1360,2100 -271,2128 267,2128 813,2145 492,2160 686,2163 2839,2198 -147,2225 65,2234 2776,2280 2475,2283 2205,2308 319,2312 -179,2358
GREEN: P2.4 Q1.3 | length 335.2
  Top Layer w15: Q1.3@1325,2291.97 1325,2386 P2.4@1332,2393 ; P2.4@1316.42,2377.42 cw(c1295.71,2356.71) 1325,2356.71 ccw(c1295.71,2356.71) P2.4@1316.42,2377.42 ; 1325,2322.93 cw(c1402.07,2322.93) 1347.58,2377.42 ccw(c1402.07,2322.93) 1325,2322.93 ; 1325,2359.15 cw(c1365.85,2359.15) 1336.97,2388.03 ccw(c1365.85,2359.15) 1325,2359.15
KEY1: U2.11 U7.4 | length 1838.4
  Top Layer w7: v1@2099,1680 2099,919.53 U7.4@2557.4,461.12 ; 2529.91,488.61 cw(c2520.54,453.62) 2551.91,471.73 ccw(c2540.53,465.16) 2543.93,477.85 ; 2542.63,478.2 ccw(c2546.13,491.29) U7.4@2553.81,480.13 ; 2546.24,484.24 cw(c2541.23,465.56) U7.4@2557.97,475.23 ; v1@2090.99,1673.99 cw(c2071.65,1654.65) 2099,1654.65 ccw(c2071.65,1654.65) v1@2090.99,1673.99 ; 2099,1664.31 cw(c2112.69,1664.31) 2103.01,1673.99 ccw(c2112.69,1664.31) 2099,1664.31 ; 2523.05,495.47 ccw(c2557.4,529.82) 2557.4,481.24 cw(c2557.4,529.82) 2523.05,495.47 ; 2535,483.52 ccw(c2557.4,505.92) 2557.4,474.24 cw(c2557.4,505.92) 2535,483.52 ; 2546.95,471.57 ccw(c2557.4,482.02) 2557.4,467.24 cw(c2557.4,482.02) 2546.95,471.57
  Bottom Layer w7: v1(2097,1680) 2114.42,1697.42 U2.11@2114.42,1758.55 ; 2111.51,1694.51 cw(c2097,1709.02) 2097,1688.5 ccw(c2097,1709.02) 2111.51,1694.51 ; 2111.51,1694.51 ccw(c2126.02,1680) 2105.5,1680 cw(c2126.02,1680) 2111.51,1694.51
KEY2: U2.12 U8.4 | length 1800
  Top Layer w7: U8.4@2059.4,459.12 v1@2059.4,1722.82 ; 2059.4,488.21 cw(c2044.09,488.21) 2054.92,477.39 ccw(c2044.09,488.21) 2059.4,488.21 ; 2059.4,488.21 ccw(c2074.72,488.21) 2063.89,477.39 cw(c2074.72,488.21) 2059.4,488.21 ; v1@2052.99,1716.81 cw(c2037.5,1701.32) 2059.4,1701.32 ccw(c2037.5,1701.32) v1@2052.99,1716.81 ; 2059.4,1703.28 cw(c2078.54,1703.28) 2065.01,1716.81 ccw(c2078.54,1703.28) 2059.4,1703.28
  Bottom Layer w7: v1@2059.36,1724.27 ccw(c2061.93,1734.54) 2071.49,1730.01 ; 2083.12,1729.99 ccw(c2086.97,1743.18) U2.12@2093.58,1731.13 ; U2.12@2094.73,1758.55 v1(2059,1722.82) ; v1(2059,1722.82) cw(c2078.88,1702.94) 2093.48,1726.97 ccw(c2078.88,1702.94) v1(2059,1722.82) ; v1@2061.2,1731.03 ccw(c2064.47,1743.24) 2070.79,1732.29 ; v1@2061.2,1731.03 ccw(c2064.47,1743.24) 2070.79,1732.29 ; v1@2061.2,1731.03 ccw(c2064.47,1743.24) 2070.79,1732.29 ; v1@2063.32,1730.14 ccw(c2067.5,1737.21) 2071.61,1730.1 ; v1@2063.32,1730.14 ccw(c2067.5,1737.21) 2071.61,1730.1 ; v1@2063.32,1730.14 ccw(c2067.5,1737.21) 2071.61,1730.1 ; v1@2067.36,1721.29 cw(c2089.17,1717.3) 2078.09,1736.5 ; v1@2067.36,1721.29 cw(c2089.17,1717.3) 2078.09,1736.5 ; v1@2067.36,1721.29 cw(c2089.17,1717.3) 2078.09,1736.5 ; v1@2067.5,1722.9 cw(c2075.71,1722.98) 2071.61,1730.1 ; v1@2067.5,1722.9 cw(c2075.71,1722.98) 2071.61,1730.1 ; v1@2067.5,1722.9 cw(c2075.71,1722.98) 2071.61,1730.1 ; 2073.51,1737.33 cw(c2059,1751.84) 2059,1731.32 ccw(c2059,1751.84) 2073.51,1737.33 ; 2073.51,1737.33 ccw(c2088.02,1722.82) 2067.5,1722.82 cw(c2088.02,1722.82) 2073.51,1737.33 ; v1@2065.3,1729.12 cw(c2083.65,1710.78) 2097.12,1732.95 ccw(c2083.65,1710.78) v1@2065.3,1729.12
LED_1: R32.2 U2.42 | length 1373.3
  Top Layer w7: R32.2@1568.63,1994.7 ccw(c1600.29,2001.18) 1591.93,1969.96 ; R32.2@1574.9,1995.51 cw(c1567.28,1958.3) 1603.97,1968.13 ; R32.2@1575,1996 1643.16,1927.84 v1(2196.16,1927.84) ; R32.2@1575.49,1996.1 ccw(c1612.7,2003.72) 1602.87,1967.03 ; R32.2@1576.3,2002.37 cw(c1569.82,1970.71) 1601.04,1979.07 ; R32.2@1599.75,1971.25 cw(c1624.51,1996) 1589.5,1996 ccw(c1624.51,1996) R32.2@1599.75,1971.25 ; R32.2@1599.75,1971.25 ccw(c1575,1946.49) 1575,1981.5 cw(c1575,1946.49) R32.2@1599.75,1971.25 ; 1611.7,1959.3 cw(c1648.41,1996) 1596.5,1996 ccw(c1648.41,1996) 1611.7,1959.3 ; 1611.7,1959.3 ccw(c1575,1922.59) 1575,1974.5 cw(c1575,1922.59) 1611.7,1959.3 ; 2175.64,1927.84 cw(c2175.64,1907.32) 2190.15,1921.83 ccw(c2175.64,1907.32) 2175.64,1927.84 ; 2175.64,1927.84 ccw(c2175.64,1948.36) 2190.15,1933.85 cw(c2175.64,1948.36) 2175.64,1927.84
  Bottom Layer w7: v1(2196.16,1927.84) U2.42@2362.45,1927.84 ; 2216.68,1927.84 cw(c2216.68,1948.36) 2202.17,1933.85 ccw(c2216.68,1948.36) 2216.68,1927.84 ; 2216.68,1927.84 ccw(c2216.68,1907.32) 2202.17,1921.83 cw(c2216.68,1907.32) 2216.68,1927.84
LED_2: R33.2 U2.41 | length 1170.2
  Top Layer w7: R33.2@1804.63,2093.7 ccw(c1836.29,2100.18) 1827.93,2068.96 ; R33.2@1810.9,2094.51 cw(c1803.28,2057.3) 1839.97,2067.13 ; R33.2@1811,2095 1913,1993 v1(2191,1993) ; R33.2@1811.49,2095.1 ccw(c1848.7,2102.72) 1838.87,2066.03 ; R33.2@1812.3,2101.37 cw(c1805.82,2069.71) 1837.04,2078.07 ; R33.2@1835.75,2070.25 cw(c1860.51,2095) 1825.5,2095 ccw(c1860.51,2095) R33.2@1835.75,2070.25 ; R33.2@1835.75,2070.25 ccw(c1811,2045.49) 1811,2080.5 cw(c1811,2045.49) R33.2@1835.75,2070.25 ; 1847.7,2058.3 cw(c1884.41,2095) 1832.5,2095 ccw(c1884.41,2095) 1847.7,2058.3 ; 1847.7,2058.3 ccw(c1811,2021.59) 1811,2073.5 cw(c1811,2021.59) 1847.7,2058.3 ; 2170.48,1993 cw(c2170.48,1972.48) 2184.99,1986.99 ccw(c2170.48,1972.48) 2170.48,1993 ; 2170.48,1993 ccw(c2170.48,2013.52) 2184.99,1999.01 cw(c2170.48,2013.52) 2170.48,1993
  Bottom Layer w7: v1(2191,1993) 2236.47,1947.53 U2.41@2362.45,1947.53 ; 2205.51,1978.49 cw(c2220.02,1993) 2199.5,1993 ccw(c2220.02,1993) 2205.51,1978.49 ; 2205.51,1978.49 ccw(c2191,1963.98) 2191,1984.5 cw(c2191,1963.98) 2205.51,1978.49
LED_3: R34.2 U2.40 | length 1018.4
  Top Layer w7: R34.2@2018.63,2177.7 ccw(c2050.29,2184.18) 2041.93,2152.96 ; R34.2@2024.9,2178.51 cw(c2017.28,2141.3) 2053.97,2151.13 ; R34.2@2025,2179 2134,2070 2162,2070 v1(2236,1996) ; R34.2@2025.49,2179.1 ccw(c2062.7,2186.72) 2052.87,2150.03 ; R34.2@2026.3,2185.37 cw(c2019.82,2153.71) 2051.04,2162.07 ; 2222.95,2008 cw(c2218.79,1992.48) v1@2234.53,1995.7 ; 2224,2009.05 ccw(c2239.52,2013.21) v1@2236.3,1997.47 ; R34.2@2049.75,2154.25 cw(c2074.51,2179) 2039.5,2179 ccw(c2074.51,2179) R34.2@2049.75,2154.25 ; R34.2@2049.75,2154.25 ccw(c2025,2129.49) 2025,2164.5 cw(c2025,2129.49) R34.2@2049.75,2154.25 ; 2061.7,2142.3 cw(c2098.41,2179) 2046.5,2179 ccw(c2098.41,2179) 2061.7,2142.3 ; 2061.7,2142.3 ccw(c2025,2105.59) 2025,2157.5 cw(c2025,2105.59) 2061.7,2142.3 ; 2221.49,2010.51 cw(c2206.98,1996) 2227.5,1996 ccw(c2206.98,1996) 2221.49,2010.51 ; 2221.49,2010.51 ccw(c2236,2025.02) 2236,2004.5 cw(c2236,2025.02) 2221.49,2010.51
  Bottom Layer w7: v1(2236,1996) 2264.79,1967.21 U2.40@2362.45,1967.21 ; 2250.51,1981.49 cw(c2265.02,1996) 2244.5,1996 ccw(c2265.02,1996) 2250.51,1981.49 ; 2250.51,1981.49 ccw(c2236,1966.98) 2236,1987.5 cw(c2236,1966.98) 2250.51,1981.49
LED_4: R35.2 U2.39 | length 747.5
  Top Layer w7: v1@2292.7,2001.47 ccw(c2289.48,2017.21) 2305,2013.05 ; v1(2293,2000) 2372,2079 R35.2@2372,2212 ; v1@2294.47,1999.7 cw(c2310.21,1996.48) 2306.05,2012 ; 2307.51,2014.51 cw(c2293,2029.02) 2293,2008.5 ccw(c2293,2029.02) 2307.51,2014.51 ; 2307.51,2014.51 ccw(c2322.02,2000) 2301.5,2000 cw(c2322.02,2000) 2307.51,2014.51 ; 2372,2160.09 cw(c2423.91,2160.09) 2387.2,2196.8 ccw(c2423.91,2160.09) 2372,2160.09 ; 2372,2160.09 ccw(c2320.09,2160.09) 2356.8,2196.8 cw(c2320.09,2160.09) 2372,2160.09 ; 2372,2176.99 cw(c2407.01,2176.99) 2382.25,2201.75 ccw(c2407.01,2176.99) 2372,2176.99 ; 2372,2176.99 ccw(c2336.99,2176.99) 2361.75,2201.75 cw(c2336.99,2176.99) 2372,2176.99
  Bottom Layer w7: v1(2293,2000) 2306.1,1986.9 ; U2.39@2362.45,1986.9 2306.1,1986.9 ; 2306.1,1986.9 cw(c2317.38,1998.17) 2301.48,1999.36 ccw(c2317.38,1998.17) 2306.1,1986.9 ; 2306.1,1986.9 ccw(c2294.83,1975.62) 2293.64,1991.52 cw(c2294.83,1975.62) 2306.1,1986.9
LED_5: R24.2 U2.16 | length 1226.4
  Top Layer w7: R24.2@1422.63,1998.7 ccw(c1454.29,2005.18) 1445.93,1973.96 ; R24.2@1428.9,1999.51 cw(c1421.28,1962.3) 1457.97,1972.13 ; R24.2@1429,2000 1560,1869 v1(1805,1869) ; R24.2@1429.49,2000.1 ccw(c1466.7,2007.72) 1456.87,1971.03 ; R24.2@1430.3,2006.37 cw(c1423.82,1974.71) 1455.04,1983.07 ; R24.2@1453.75,1975.25 cw(c1478.51,2000) 1443.5,2000 ccw(c1478.51,2000) R24.2@1453.75,1975.25 ; R24.2@1453.75,1975.25 ccw(c1429,1950.49) 1429,1985.5 cw(c1429,1950.49) R24.2@1453.75,1975.25 ; 1465.7,1963.3 cw(c1502.41,2000) 1450.5,2000 ccw(c1502.41,2000) 1465.7,1963.3 ; 1465.7,1963.3 ccw(c1429,1926.59) 1429,1978.5 cw(c1429,1926.59) 1465.7,1963.3 ; 1784.48,1869 cw(c1784.48,1848.48) 1798.99,1862.99 ccw(c1784.48,1848.48) 1784.48,1869 ; 1784.48,1869 ccw(c1784.48,1889.52) 1798.99,1875.01 cw(c1784.48,1889.52) 1784.48,1869
  Bottom Layer w7: v1@1805,1868.79 U2.16@2043.55,1868.79 ; v1@1811.01,1862.99 cw(c1825.01,1848.99) 1825.01,1868.79 ccw(c1825.01,1848.99) v1@1811.01,1862.99 ; v1@1811.01,1875.01 ccw(c1826.03,1890.03) 1826.03,1868.79 cw(c1826.03,1890.03) v1@1811.01,1875.01
LED_6: R23.2 U2.15 | length 1374.9
  Top Layer w7: R23.2@1288.63,1999.7 ccw(c1320.29,2006.18) 1311.93,1974.96 ; R23.2@1294.9,2000.51 cw(c1287.28,1963.3) 1323.97,1973.13 ; R23.2@1295,2001 1456,1840 v1@1703,1840 ; R23.2@1295.49,2001.1 ccw(c1332.7,2008.72) 1322.87,1972.03 ; R23.2@1296.3,2007.37 cw(c1289.82,1975.71) 1321.04,1984.07 ; R23.2@1319.75,1976.25 cw(c1344.51,2001) 1309.5,2001 ccw(c1344.51,2001) R23.2@1319.75,1976.25 ; R23.2@1319.75,1976.25 ccw(c1295,1951.49) 1295,1986.5 cw(c1295,1951.49) R23.2@1319.75,1976.25 ; 1331.7,1964.3 cw(c1368.41,2001) 1316.5,2001 ccw(c1368.41,2001) 1331.7,1964.3 ; 1331.7,1964.3 ccw(c1295,1927.59) 1295,1979.5 cw(c1295,1927.59) 1331.7,1964.3 ; 1678.24,1840 cw(c1678.24,1809.24) 1699.99,1830.99 ccw(c1678.24,1809.24) 1678.24,1840 ; 1692.72,1840 ccw(c1692.72,1850.28) 1699.99,1843.01 cw(c1692.72,1850.28) 1692.72,1840
  Bottom Layer w7: v1(1706,1837) 1920,1837 1932.1,1849.1 U2.15@2043.55,1849.1 ; 1726.52,1837 cw(c1726.52,1857.52) 1712.01,1843.01 ccw(c1726.52,1857.52) 1726.52,1837 ; 1726.52,1837 ccw(c1726.52,1816.48) 1712.01,1830.99 cw(c1726.52,1816.48) 1726.52,1837
LED_7: R25.2 U2.14 | length 1571.4
  Top Layer w7: R25.2@1136.63,1999.7 ccw(c1168.29,2006.18) 1159.93,1974.96 ; R25.2@1142.9,2000.51 cw(c1135.28,1963.3) 1171.97,1973.13 ; R25.2@1143,2001 1332.5,1811.5 v1(1631.5,1811.5) ; R25.2@1143.49,2001.1 ccw(c1180.7,2008.72) 1170.87,1972.03 ; R25.2@1144.3,2007.37 cw(c1137.82,1975.71) 1169.04,1984.07 ; R25.2@1167.75,1976.25 cw(c1192.51,2001) 1157.5,2001 ccw(c1192.51,2001) R25.2@1167.75,1976.25 ; R25.2@1167.75,1976.25 ccw(c1143,1951.49) 1143,1986.5 cw(c1143,1951.49) R25.2@1167.75,1976.25 ; 1179.7,1964.3 cw(c1216.41,2001) 1164.5,2001 ccw(c1216.41,2001) 1179.7,1964.3 ; 1179.7,1964.3 ccw(c1143,1927.59) 1143,1979.5 cw(c1143,1927.59) 1179.7,1964.3 ; 1610.98,1811.5 cw(c1610.98,1790.98) 1625.49,1805.49 ccw(c1610.98,1790.98) 1610.98,1811.5 ; 1610.98,1811.5 ccw(c1610.98,1832.02) 1625.49,1817.51 cw(c1610.98,1832.02) 1610.98,1811.5
  Bottom Layer w7: v1(1631.5,1811.5) 1635,1808 1941,1808 1962.42,1829.42 U2.14@2043.55,1829.42 ; 1643.57,1808 cw(c1643.57,1823.57) 1632.56,1812.56 ccw(c1643.57,1823.57) 1643.57,1808 ; 1643.57,1808 ccw(c1643.57,1799.43) 1637.51,1805.49 cw(c1643.57,1799.43) 1643.57,1808 ; v1@1637.51,1817.51 ccw(c1660.47,1840.47) 1660.47,1808 cw(c1660.47,1840.47) v1@1637.51,1817.51
LED_8: R26.2 U2.13 | length 1806.1
  Top Layer w7: R26.2@984.63,2005.7 ccw(c1016.29,2012.18) 1007.93,1980.96 ; R26.2@990.9,2006.51 cw(c983.28,1969.3) 1019.97,1979.13 ; R26.2@991,2007 1228,1770 v1(2038,1770) ; R26.2@991.49,2007.1 ccw(c1028.7,2014.72) 1018.87,1978.03 ; R26.2@992.3,2013.37 cw(c985.82,1981.71) 1017.04,1990.07 ; R26.2@1015.75,1982.25 cw(c1040.51,2007) 1005.5,2007 ccw(c1040.51,2007) R26.2@1015.75,1982.25 ; R26.2@1015.75,1982.25 ccw(c991,1957.49) 991,1992.5 cw(c991,1957.49) R26.2@1015.75,1982.25 ; 1027.7,1970.3 cw(c1064.41,2007) 1012.5,2007 ccw(c1064.41,2007) 1027.7,1970.3 ; 1027.7,1970.3 ccw(c991,1933.59) 991,1985.5 cw(c991,1933.59) 1027.7,1970.3 ; 2017.48,1770 cw(c2017.48,1749.48) 2031.99,1763.99 ccw(c2017.48,1749.48) 2017.48,1770 ; 2017.48,1770 ccw(c2017.48,1790.52) 2031.99,1776.01 cw(c2017.48,1790.52) 2017.48,1770
  Bottom Layer w7: 2036.09,1783.11 ccw(c2043.81,1778.65) v1@2038.84,1771.24 ; 2039.84,1789.6 ccw(c2048.01,1784.88) v1@2042.74,1777.05 ; U2.13@2041.47,1808.53 cw(c2031.99,1803.06) 2042.56,1800.23 ; v1@2043.55,1775.55 U2.13@2043.55,1809.73 ; v1@2031.99,1776.01 ccw(c2004.08,1803.92) 2043.55,1803.92 cw(c2004.08,1803.92) v1@2031.99,1776.01 ; v1@2036.94,1771.06 ccw(c2020.98,1787.02) 2043.55,1787.02 cw(c2020.98,1787.02) v1@2036.94,1771.06
NetC4_2: C4.2 U2.5 Y1.2 | length 3435.7
  Bottom Layer w7: U2.5@2232.53,1758.55 2232.53,1707.47 2278.26,1661.74 2278.98,1661.74 2285.13,1655.59 2285.13,1654.87 ; Y1.2@2375,1565 2285.13,1654.87 ; C4.2@2378.89,1504.01 ccw(c2347.76,1527.69) 2385.94,1536.16 ccw(c2423.97,1544.6) C4.2@2405.95,1510.06 ; C4.2@2383.95,1508.81 ccw(c2372.68,1525.46) 2392.52,1528.73 ccw(c2418.08,1532.95) C4.2@2406.02,1510.02 ; C4.2@2384.46,1499.78 ccw(c2363.49,1515.72) 2389.21,1521.43 ; C4.2@2387.87,1503.01 ccw(c2379.42,1515.5) 2394.3,1517.95 ; 2389.19,1521.48 ccw(c2414.88,1527.18) C4.2@2402.71,1503.85 ; C4.2@2396,1491 Y1.2@2396,1594.74 ; 2285.13,1654.87 ccw(c2339.89,1709.62) 2373.96,1640.09 cw(c2339.89,1709.62) 2285.13,1654.87 ; 2396,1526.01 cw(c2360.99,1526.01) 2385.75,1501.25 ccw(c2360.99,1526.01) 2396,1526.01 ; 2396,1526.01 ccw(c2431.01,1526.01) 2406.25,1501.25 cw(c2431.01,1526.01) 2396,1526.01 ; 2396,1542.91 cw(c2344.09,1542.91) 2380.8,1506.2 ccw(c2344.09,1542.91) 2396,1542.91 ; 2396,1542.91 ccw(c2447.91,1542.91) 2411.2,1506.2 cw(c2447.91,1542.91) 2396,1542.91 ; 2292.06,1647.94 ccw(c2344.44,1700.33) 2377.04,1633.8 cw(c2344.44,1700.33) 2292.06,1647.94 ; 2298.98,1641.02 ccw(c2349,1691.03) 2380.12,1627.51 cw(c2349,1691.03) 2298.98,1641.02 ; 2305.91,1634.09 ccw(c2353.55,1681.73) 2383.2,1621.23 cw(c2353.55,1681.73) 2305.91,1634.09 ; 2312.84,1627.16 ccw(c2358.11,1672.43) 2386.28,1614.94 cw(c2358.11,1672.43) 2312.84,1627.16 ; 2319.76,1620.24 ccw(c2362.66,1663.14) 2389.36,1608.66 cw(c2362.66,1663.14) 2319.76,1620.24 ; 2326.69,1613.31 ccw(c2367.22,1653.84) 2392.44,1602.37 cw(c2367.22,1653.84) 2326.69,1613.31 ; 2333.62,1606.39 ccw(c2371.77,1644.54) 2395.52,1596.08 cw(c2371.77,1644.54) 2333.62,1606.39 ; 2340.54,1599.46 ccw(c2376.33,1635.25) 2398.6,1589.8 cw(c2376.33,1635.25) 2340.54,1599.46 ; 2347.47,1592.53 ccw(c2380.88,1625.95) 2401.68,1583.51 cw(c2380.88,1625.95) 2347.47,1592.53 ; Y1.2@2354.39,1585.61 ccw(c2385.44,1616.65) 2404.76,1577.23 cw(c2385.44,1616.65) Y1.2@2354.39,1585.61 ; Y1.2@2361.32,1578.68 ccw(c2389.99,1607.36) 2407.84,1570.94 cw(c2389.99,1607.36) Y1.2@2361.32,1578.68 ; Y1.2@2364.45,1566.69 cw(c2288.98,1490.81) 2396,1490.81 ccw(c2288.98,1490.81) Y1.2@2364.45,1566.69 ; Y1.2@2368.25,1571.75 ccw(c2394.55,1598.06) 2410.92,1564.65 cw(c2394.55,1598.06) Y1.2@2368.25,1571.75 ; Y1.2@2369.38,1571.66 cw(c2305.72,1507.64) 2396,1507.64 ccw(c2305.72,1507.64) Y1.2@2369.38,1571.66 ; Y1.2@2374.32,1576.62 cw(c2322.46,1524.48) 2396,1524.48 ccw(c2322.46,1524.48) Y1.2@2374.32,1576.62 ; Y1.2@2375.17,1564.83 ccw(c2399.1,1588.76) 2414,1558.37 cw(c2399.1,1588.76) Y1.2@2375.17,1564.83 ; Y1.2@2379.25,1581.58 cw(c2339.21,1541.31) 2396,1541.31 ccw(c2339.21,1541.31) Y1.2@2379.25,1581.58 ; 2396,1520.64 cw(c2461.23,1520.64) 2415.1,1566.76 ccw(c2461.23,1520.64) 2396,1520.64 ; 2396,1537.54 cw(c2444.33,1537.54) 2410.15,1571.71 ccw(c2444.33,1537.54) 2396,1537.54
